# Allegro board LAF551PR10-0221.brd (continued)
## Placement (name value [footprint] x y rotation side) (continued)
PC214  0.1U_0402_10V7K  [C_0402]  95.88 47.23 0 bottom
PC215  220U 2.5V Y D2 ESR9M H1.9 SX  [C_D2]  91.41 30.94 270 bottom
PC216  1000P_0402_50V7K  [C_0402]  87.72 36.95 90 top
PC217  0.1U_0402_25V6  [C_0402]  103.17 53.7 270 top
PC218  0.1U_0402_25V6  [C_0402]  107.9 56.45 270 top
PC300  0.1U_0402_16V7K  [C_0402]  241.83 17.83 180 top
PC301  0.1U_0402_25V6  [C_0402]  259.79 23.04 0 top
PC302  2200P_0402_50V7K  [C_0402]  259.22 22.08 270 top
PC303  10U_0805_25V6K~D  [C_0805]  260.08 19.87 180 top
PC304  10U_0805_25V6K~D  [C_0805]  260.08 18.15 180 top
PC305  0.1U_0603_25V7K  [C_0603]  248.29 21.77 270 top
PC306  220U 2.5V Y D2 ESR9M H1.9 SX  [C_D2]  244.59 24.59 270 bottom
PC307  220U 2.5V Y D2 ESR9M H1.9 SX  [C_D2]  239.82 24.59 270 bottom
PC308  1U_0603_6.3V6M  [C_0603]  247.85 19.29 270 top
PC309  680P_0402_50V7K  [C_0402]  257.49 19.1 0 bottom
PC310  1U_0402_25V6K  [C_0402]  258.33 22.05 270 top
PC311  1000P_0402_50V7K  [C_0402]  259.79 23.93 0 top
PC500  2200P_0402_50V7K  [C_0402]  126.88 136.6 90 top
PC501  0.01UF_0402_25V7K  [C_0402]  125.92 133.4 180 bottom
PC502  10U_0402_6.3V6M  [C_0402]  122.18 139.93 270 bottom
PC503  1000P_0402_50V7K  [C_0402]  127.75 135.28 180 top
PC504  3300P_0402_25V7K  [C_0402]  124.8 139.2 90 bottom
PC505  2200P_0402_50V7K  [C_0402]  125.92 134.32 180 bottom
PC506  470P_0402_50V8J  [C_0402]  123.91 139.97 270 bottom
PC507  1000P_0402_50V7K  [C_0402]  126.55 139.65 180 bottom
PC508  1000P_0402_50V7K  [C_0402]  127.75 136.6 90 top
PC509  0.015U_0402_25V7K  [C_0402]  128.81 135.72 0 bottom
PC510  100P_0402_50V8J  [C_0402]  127.39 140.41 270 bottom
PC511  1000P_0402_50V7K  [C_0402]  129.73 136.58 180 top
PC512  2200P_0402_50V7K  [C_0402]  129.73 139.63 180 top
PC513  1000P_0402_50V7K  [C_0402]  119.69 135.49 270 top
PC514  2200P_0402_50V7K  [C_0402]  120.53 137.37 180 bottom
PC515  15P_0402_50V8J  [C_0402]  129.71 141.35 180 bottom
PC516  470P_0402_50V8J  [C_0402]  129.75 140.52 180 top
PC517  2200P_0402_50V7K  [C_0402]  129.73 140.49 180 bottom
PC518  470P_0402_50V8J  [C_0402]  117.05 133.68 90 top
PC519  15P_0402_50V8J  [C_0402]  119.44 141.91 90 bottom
PC520  470P_0402_50V8J  [C_0402]  127.36 141.28 180 bottom
PC521  2200P_0402_50V7K  [C_0402]  118.55 143.69 0 bottom
PC522  470P_0402_50V8J  [C_0402]  120.74 141.43 0 bottom
PC523  100P_0402_50V8J  [C_0402]  128.86 143.28 90 bottom
PC524  1000P_0402_50V7K  [C_0402]  128.86 144.2 270 top
PC525  0.22U_0402_25V6K  [C_0402]  126.53 143.89 0 bottom
PC526  100P_0402_50V8J  [C_0402]  120.34 144.25 90 bottom
PC527  0.22U_0402_25V6K  [C_0402]  120.4 146.36 0 bottom
PC528  680P_0402_50V7K  [C_0402]  121.22 144.25 90 bottom
PC529  0.1U_0402_25V6  [C_0402]  126.6 145.52 180 bottom
PC530  0.01U_0402_50V7K  [C_0402]  126.97 148.79 270 top
PC531  0.1U_0402_25V6  [C_0402]  122.41 148.21 180 bottom
PC532  1U_0603_10V6K  [C_0603]  125.92 147.93 90 top
PC533  0.1U_0402_25V6  [C_0402]  129.42 145.49 180 bottom
PC534  0.1U_0402_25V6  [C_0402]  119.74 148.21 0 bottom
PC535  0.1U_0402_25V6  [C_0402]  129.42 146.36 180 bottom
PC536  0.1U_0402_25V6  [C_0402]  129.41 148.12 180 bottom
PC537  0.1U_0402_25V6  [C_0402]  129.42 149.89 180 bottom
PC539  100U_25V_M  [C_ECST250ADA101MF611]  160.82 156.74 270 bottom
PC540  1U_0402_16V6K  [C_0402]  151.02 149.66 180 top
PC541  0.22U_0603_25V7K  [C_0603]  152.23 150.97 90 bottom
PC542  100U_25V_M  [C_ECST250ADA101MF611]  153.78 156.74 270 bottom
PC543  10U_0805_25V6K  [C_0805]  152.15 148.34 270 top
PC544  10U_0805_25V6K  [C_0805]  153.88 148.34 270 top
PC545  10U_0805_25V6K  [C_0805]  153.89 150.1 180 top
PC546  0.1U_0402_25V6  [C_0402]  156.47 147.68 270 top
PC547  2200P_0402_50V7K  [C_0402]  155.08 147.73 270 bottom
PC548  33P_0603_50V8J  [C_0603]  152.85 141.68 0 top
PC549  1U_0402_16V6K  [C_0402]  157.34 146.76 90 top
PC550  0.22U_0603_25V7K  [C_0603]  160.03 147.97 90 bottom
PC551  10U_0805_25V6K  [C_0805]  160.08 145.2 270 top
PC552  10U_0805_25V6K  [C_0805]  161.78 145.22 270 top
PC553  10U_0805_25V6K  [C_0805]  160.18 146.33 90 top
PC554  0.1U_0402_25V6  [C_0402]  158.8 146.75 270 top
PC555  2200P_0402_50V7K  [C_0402]  162.8 145.14 270 bottom
PC556  33P_0603_50V8J  [C_0603]  160.67 137.86 0 top
PC557  1U_0402_16V6K  [C_0402]  166.81 143.68 90 top
PC558  0.22U_0603_25V7K  [C_0603]  167.64 147.98 90 bottom
PC559  10U_0805_25V6K  [C_0805]  170.19 145.11 270 top
PC560  10U_0805_25V6K  [C_0805]  170.25 146.23 90 top
PC561  10U_0805_25V6K  [C_0805]  168.47 145.15 270 top
PC562  0.1U_0402_25V6  [C_0402]  170.42 145.65 270 bottom
PC563  2200P_0402_50V7K  [C_0402]  171.28 145.62 270 bottom
PC564  33P_0603_50V8J  [C_0603]  168.27 137.86 0 top
PC565  10U_0805_25V6K  [C_0805]  145.39 149.79 180 top
PC566  1U_0402_16V6K  [C_0402]  142.71 149.34 180 top
PC567  0.22U_0603_25V7K  [C_0603]  143.62 151.57 90 bottom
PC568  10U_0805_25V6K  [C_0805]  143.88 148.35 270 top
PC569  10U_0805_25V6K  [C_0805]  145.59 148.35 270 top
PC570  680P_0603_50V7K  [C_0603]  145.39 141.62 0 top
PC571  0.1U_0402_25V6  [C_0402]  147.43 147.53 270 bottom
PC572  2200P_0402_50V7K  [C_0402]  146.39 149.65 90 top
PC573  1U_0402_16V6K  [C_0402]  174.7 146.13 180 top
PC574  0.22U_0603_25V7K  [C_0603]  176.15 148.03 90 bottom
PC575  10U_0805_25V6K  [C_0805]  176.87 144.82 270 top
PC576  10U_0805_25V6K  [C_0805]  178.6 144.82 270 top
PC577  10U_0805_25V6K  [C_0805]  177.24 145.94 90 top
PC578  0.1U_0402_25V6  [C_0402]  178.42 148.56 0 bottom
PC579  2200P_0402_50V7K  [C_0402]  178.42 147.67 0 bottom
PC580  33P_0603_50V8J  [C_0603]  177.18 137.86 0 top
PC581  2200P_0402_50V7K  [C_0402]  185.57 148.02 0 bottom
PC582  0.1U_0402_25V6  [C_0402]  186.76 146.89 45 bottom
PC583  10U_0805_25V6K  [C_0805]  184.79 144.86 270 top
PC584  10U_0805_25V6K  [C_0805]  185.71 149.32 0 bottom
PC585  10U_0805_25V6K  [C_0805]  183.08 144.86 270 top
PC586  0.22U_0603_25V7K  [C_0603]  183.33 147.96 90 bottom
PC587  680P_0603_50V7K  [C_0603]  184.59 136.2 0 top
PC588  1U_0402_16V6K  [C_0402]  180.81 146.49 0 top
PC589  2200P_0402_50V7K  [C_0402]  118.64 119.18 180 bottom
PC590  0.22U_0402_10V6K  [C_0402]  124.58 119.5 0 bottom
PC591  680P_0603_50V7K  [C_0603]  118.44 109.91 270 bottom
PC592  10U_0805_25V6K  [C_0805]  120 121.53 0 bottom
PC593  0.1U_0603_25V7K  [C_0603]  119.45 114.93 0 bottom
PC594  0.1U_0402_25V6  [C_0402]  118.64 118.29 180 bottom
PC596  22U_0603_6.3V6M  [C_0603]  122.62 105.66 180 bottom
PC597  22U_0603_6.3V6M  [C_0603]  122.62 106.99 180 bottom
PC598  22U_0603_6.3V6M  [C_0603]  124.78 106.99 0 bottom
PC599  22U_0603_6.3V6M  [C_0603]  124.78 105.66 0 bottom
PC701  0.1U_0402_25V6  [C_0402]  58.05 30.47 180 top
PC702  0.047U_0402_25V7K  [C_0402]  61.78 25.01 0 top
PC703  0.1U_0402_25V6  [C_0402]  64.33 29.01 270 top
PC704  2200P_0402_50V7K  [C_0402]  63.45 29.01 270 top
PC705  10U_0805_25V6K~D  [C_0805]  65.73 28.88 270 top
PC706  10U_0805_25V6K~D  [C_0805]  67.51 28.88 270 top
PC707  0.1U_0603_25V7K  [C_0603]  58.37 24.41 90 bottom
PC708  0.1U_0402_25V6  [C_0402]  58.48 27.55 0 bottom
PC709  0.01UF_0402_25V7K  [C_0402]  59.64 26.36 270 bottom
PC710  2.2U_0603_10V7K  [C_0603]  59.23 23.17 180 bottom
PC711  1U_0603_25V6K  [C_0603]  59.44 24.44 0 bottom
PC712  22U_0805_25V6M  [C_0805]  82.47 28.71 90 bottom
PC713  22U_0805_25V6M  [C_0805]  84.18 28.71 90 bottom
PC714  22U_0805_25V6M  [C_0805]  86.03 28.74 90 bottom
PC715  680P_0402_50V7K  [C_0402]  63.76 22.84 90 top
PC716  0.1U_0402_25V6  [C_0402]  57.4 17.71 0 top
PC717  0.1U_0402_25V6  [C_0402]  58.31 18.6 180 top
PC718  100P_0402_50V8J  [C_0402]  52.96 26.49 0 top
PC719  0.01UF_0402_25V7K  [C_0402]  56.34 26.66 270 bottom
PC720  100P_0402_50V8J  [C_0402]  52.97 25.6 0 top
PC721  0.1U_0402_25V6  [C_0402]  56.52 18.61 270 top
PC722  1000P_0402_50V7K  [C_0402]  70.11 42.36 180 top
PC723  1000P_0402_50V7K  [C_0402]  69.92 35.17 180 top
PC725  0.022U_0603_25V7K  [C_0603]  79.93 30.14 90 top
PC726  1000P_0402_50V7K  [C_0402]  62.56 29.02 270 top
PC727  1U_0402_25V6K  [C_0402]  61.67 29.02 270 top
PC800  10U_0805_25V6K~D  [C_0805]  245.12 40.57 90 bottom
PC801  0.1U_0402_16V7K  [C_0402]  238.08 41.65 180 bottom
PC802  680P_0402_50V7K  [C_0402]  247.8 47.11 0 bottom
PC803  2.2U_0402_16V6K  [C_0402]  241.31 44.58 270 top
PC804  22U_0603_6.3V6M  [C_0603]  240.42 48.38 90 bottom
PC805  22U_0603_6.3V6M  [C_0603]  239.15 48.38 90 bottom
PC806  680P_0402_50V7K  [C_0402]  234.44 45.84 0 bottom
PC807  2.2U_0402_16V6K  [C_0402]  122.61 115.24 0 bottom
PC808  0.1U_0603_25V7K  [C_0603]  248.62 44.75 180 bottom
PC809  330P_0402_50V7K  [C_0402]  237.17 45.2 0 bottom
PC810  10U_0805_25V6K~D  [C_0805]  229.93 37.2 0 bottom
PC811  0.1U_0402_16V7K  [C_0402]  226.07 40.36 90 bottom
PC812  22U_0603_6.3V6M  [C_0603]  224.86 46.61 270 bottom
PC813  22U_0603_6.3V6M  [C_0603]  223.59 46.61 270 bottom
PC814  10U_0805_25V6K~D  [C_0805]  229.85 38.92 0 bottom
PC815  22U_0603_6.3V6M  [C_0603]  236.67 48.38 90 bottom
PC816  22U_0603_6.3V6M  [C_0603]  237.94 48.38 90 bottom
PC817  1U_0603_6.3V6M  [C_0603]  239.14 46.1 0 bottom
PC818  330P_0402_50V7K  [C_0402]  124.65 125.17 180 bottom
PC819  330P_0402_50V7K  [C_0402]  222.51 44.64 270 bottom
PC820  22U_0603_6.3V6M  [C_0603]  224.86 47.58 90 bottom
PC821  1U_0603_6.3V6M  [C_0603]  226.13 44.12 180 bottom
PC822  2.2U_0402_16V6K  [C_0402]  229.56 45.15 180 bottom
PC823  0.1U_0603_25V7K  [C_0603]  234.07 44.25 180 bottom
PC824  22U_0603_6.3V6M  [C_0603]  223.59 47.58 90 bottom
PC1000  220U_D7_2VM_R6M  [C_EEFSS0D221R]  164.07 127.12 0 bottom
PC1001  220U 2.5V Y D2 ESR9M H1.9 SX  [C_D2]  170.89 127.15 0 top
PC1002  220U 2.5V Y D2 ESR9M H1.9 SX  [C_D2]  161.7 127.18 180 top
PC1003  47U_0603_6.3V6M  [C_0603]  177.04 128.48 270 bottom
PC1004  47U_0603_6.3V6M  [C_0603]  175.14 128.48 270 bottom
PC1005  47U_0805_6.3V6M  [C_0805]  164.77 108.89 0 top
PC1006  47U_0603_6.3V6M  [C_0603]  178.95 128.48 270 bottom
PC1007  220U 2.5V Y D2 ESR9M H1.9 SX  [C_D2]  145.91 132.2 0 top
PC1008  220U_D7_2VM_R6M  [C_EEFSS0D221R]  143.11 128.01 0 bottom
PC1009  220U_D7_2VM_R6M  [C_EEFSS0D221R]  151.67 127.31 180 top
PC1010  220U_D7_2VM_R6M  [C_EEFSS0D221R]  155.58 113.42 0 top
PC1011  47U_0603_6.3V6M  [C_0603]  136.6 110.86 180 top
PC1012  47U_0603_6.3V6M  [C_0603]  145.49 113.27 0 top
PC1013  47U_0603_6.3V6M  [C_0603]  136.34 115.69 180 top
PC1014  47U_0805_6.3V6M  [C_0805]  184.64 130.48 0 top
PC1015  47U_0805_6.3V6M  [C_0805]  184.64 132.2 0 top
PC1016  47U_0805_6.3V6M  [C_0805]  179.68 130.55 180 top
PC1017  220U_D2_2.5VY_R9M  [C_D2]  180.83 127.18 0 top
PC1018  47U_0805_6.3V6M  [C_0805]  164.77 110.61 0 top
PC1019  10U_0402_6.3V6M  [C_0402]  165.5 113.75 0 top
PC1020  22U_0603_6.3V6M  [C_0603]  156.86 109.46 0 top
PC1021  22U_0603_6.3V6M  [C_0603]  156.86 108.26 0 top
PC1022  22U_0603_6.3V6M  [C_0603]  155.91 109.46 180 top
PC1023  22U_0603_6.3V6M  [C_0603]  155.91 108.26 180 top
PC1024  22U_0603_6.3V6M  [C_0603]  160.61 108.26 180 top
PC1025  22U_0603_6.3V6M  [C_0603]  160.61 109.46 180 top
PC1026  22U_0603_6.3V6M  [C_0603]  161.56 109.46 0 top
PC1027  22U_0603_6.3V6M  [C_0603]  161.56 108.26 0 top
PC1028  22U_0603_6.3V6M  [C_0603]  140.73 109.84 0 top
PC1029  22U_0603_6.3V6M  [C_0603]  138.38 109.84 0 top
PC1030  22U_0603_6.3V6M  [C_0603]  140.87 106.93 180 top
PC1031  22U_0603_6.3V6M  [C_0603]  143.08 109.84 0 top
PC1032  22U_0603_6.3V6M  [C_0603]  144.69 108.22 180 top
PC1033  22U_0603_6.3V6M  [C_0603]  140.87 108.18 180 top
PC1034  22U_0603_6.3V6M  [C_0603]  144.69 106.9 180 top
PC1036  10U_0402_6.3V6M  [C_0402]  164.68 112.83 180 top
PC1037  10U_0402_6.3V6M  [C_0402]  164.76 116.54 180 top
PC1038  10U_0402_6.3V6M  [C_0402]  165.58 116.26 0 top
PC1039  10U_0402_6.3V6M  [C_0402]  164.68 113.72 180 top
PC1040  10U_0402_6.3V6M  [C_0402]  164.68 111.94 180 top
PC1041  10U_0402_6.3V6M  [C_0402]  165.55 111.94 0 top
PC1042  1U_0201_6.3V6M  [C_0201]  164.82 115.82 180 top
PC1043  22U_0603_6.3V6M  [C_0603]  183.51 127.83 0 bottom
PC1044  22U_0603_6.3V6M  [C_0603]  165.14 114.78 0 top
PC1045  10U_0402_6.3V6M  [C_0402]  150.48 115.58 0 top
PC1046  10U_0402_6.3V6M  [C_0402]  147.17 110.01 180 top
PC1047  10U_0402_6.3V6M  [C_0402]  153.2 110.29 180 top
PC1048  10U_0402_6.3V6M  [C_0402]  147.17 110.88 180 top
PC1049  10U_0402_6.3V6M  [C_0402]  153.13 113.32 180 top
PC1050  10U_0402_6.3V6M  [C_0402]  148.02 111.23 0 top
PC1051  10U_0402_6.3V6M  [C_0402]  150.47 113.31 0 top
PC1052  10U_0402_6.3V6M  [C_0402]  146.9 104.58 180 top
PC1053  10U_0402_6.3V6M  [C_0402]  157.33 104.8 180 top
PC1054  10U_0402_6.3V6M  [C_0402]  157.25 106.13 180 top
PC1055  10U_0402_6.3V6M  [C_0402]  153.37 104.93 0 top
PC1056  10U_0402_6.3V6M  [C_0402]  158.09 106.13 0 top
PC1057  10U_0402_6.3V6M  [C_0402]  157.41 107.22 0 top
PC1058  10U_0402_6.3V6M  [C_0402]  153.13 114.5 180 top
PC1059  10U_0402_6.3V6M  [C_0402]  140.87 112.87 0 top
PC1060  10U_0402_6.3V6M  [C_0402]  145.87 114.35 0 top
PC1061  10U_0402_6.3V6M  [C_0402]  143.33 113.97 0 top
PC1062  10U_0402_6.3V6M  [C_0402]  145.57 112.21 0 top
PC1063  10U_0402_6.3V6M  [C_0402]  145.85 116.01 0 top
PC1064  10U_0402_6.3V6M  [C_0402]  140.87 111.43 0 top
PC1065  10U_0402_6.3V6M  [C_0402]  138.6 111.49 0 top
PC1066  10U_0402_6.3V6M  [C_0402]  138.62 112.86 0 top
PC1067  10U_0402_6.3V6M  [C_0402]  143.19 112.23 0 top
PC1068  10U_0402_6.3V6M  [C_0402]  143.51 116.04 0 top
PC1071  10U_0402_6.3V6M  [C_0402]  160.07 107.22 180 top
PC1072  10U_0402_6.3V6M  [C_0402]  159.82 106.12 0 top
PC1073  10U_0402_6.3V6M  [C_0402]  148.02 109.65 0 top
PC1074  10U_0402_6.3V6M  [C_0402]  147.98 112.57 0 top
PC1075  10U_0402_6.3V6M  [C_0402]  151.58 104.34 180 top
PC1076  10U_0402_6.3V6M  [C_0402]  163.3 106.99 0 top
PC1077  10U_0402_6.3V6M  [C_0402]  162.46 106.12 180 top
PC1078  10U_0402_6.3V6M  [C_0402]  152.29 108.43 180 top
PC1079  10U_0402_6.3V6M  [C_0402]  163.3 106.12 0 top
PC1080  10U_0402_6.3V6M  [C_0402]  150.5 112.09 0 top
PC1081  10U_0402_6.3V6M  [C_0402]  165.94 106.99 180 top
PC1082  10U_0402_6.3V6M  [C_0402]  150.51 110.78 0 top
PC1083  10U_0402_6.3V6M  [C_0402]  148.55 114.75 0 top
PC1084  10U_0402_6.3V6M  [C_0402]  155.35 106.2 180 top
PC1097  1U_0201_6.3V6M  [C_0201]  163.12 102.92 180 top
PC1098  1U_0201_6.3V6M  [C_0201]  164.62 104.94 180 top
PC1099  1U_0201_6.3V6M  [C_0201]  165.81 126.74 270 top
PC1100  1U_0201_6.3V6M  [C_0201]  155.1 106.91 180 top
PC1101  1U_0201_6.3V6M  [C_0201]  165.27 104.94 0 top
PC1102  1U_0201_6.3V6M  [C_0201]  158.65 103.79 90 top
PC1103  1U_0201_6.3V6M  [C_0201]  159.22 103.79 90 top
PC1104  1U_0201_6.3V6M  [C_0201]  162.89 103.49 180 top
PC1105  1U_0201_6.3V6M  [C_0201]  162.23 110.8 180 top
PC1106  1U_0201_6.3V6M  [C_0201]  166.57 105.68 0 top
PC1107  1U_0201_6.3V6M  [C_0201]  161.98 116.07 180 top
PC1108  1U_0201_6.3V6M  [C_0201]  161.98 116.64 180 top
PC1109  1U_0201_6.3V6M  [C_0201]  162.57 116.64 0 top
PC1110  1U_0201_6.3V6M  [C_0201]  162.57 116.07 0 top
PC1111  1U_0201_6.3V6M  [C_0201]  160.44 110.8 0 top
PC1123  1U_0201_6.3V6M  [C_0201]  155.37 116.08 0 top
PC1124  1U_0201_6.3V6M  [C_0201]  160.19 116.06 0 top
PC1125  1U_0201_6.3V6M  [C_0201]  166.66 107.12 90 top
PC1126  1U_0201_6.3V6M  [C_0201]  166.57 105.12 0 top
PC1127  1U_0201_6.3V6M  [C_0201]  157.77 116.07 0 top
PC1128  1U_0201_6.3V6M  [C_0201]  157.15 116.64 180 top
PC1129  1U_0201_6.3V6M  [C_0201]  164.62 104.37 180 top
PC1130  1U_0201_6.3V6M  [C_0201]  157.15 116.07 180 top
PC1131  1U_0201_6.3V6M  [C_0201]  159.56 116.64 180 top
PC1132  1U_0201_6.3V6M  [C_0201]  154.74 116.63 180 top
PC1133  1U_0201_6.3V6M  [C_0201]  154.74 116.07 180 top
PC1134  1U_0201_6.3V6M  [C_0201]  163.74 102.92 0 top
PC1135  1U_0201_6.3V6M  [C_0201]  148.45 115.46 0 top
PC1136  1U_0201_6.3V6M  [C_0201]  162.86 110.8 0 top
PC1137  1U_0201_6.3V6M  [C_0201]  160.44 104.95 0 top
PC1138  1U_0201_6.3V6M  [C_0201]  142.74 116.13 180 top
PC1139  1U_0201_6.3V6M  [C_0201]  140.3 114.6 180 top
PC1140  1U_0201_6.3V6M  [C_0201]  144.03 105.71 180 top
PC1141  1U_0201_6.3V6M  [C_0201]  140.28 116.18 180 top
PC1142  1U_0201_6.3V6M  [C_0201]  140.97 114.14 0 top
PC1143  1U_0201_6.3V6M  [C_0201]  141.57 105.58 180 top
PC1144  1U_0201_6.3V6M  [C_0201]  140.95 115.61 0 top
PC1145  1U_0201_6.3V6M  [C_0201]  138.54 114.45 0 top
PC1146  1U_0201_6.3V6M  [C_0201]  139.18 105.26 180 top
PC1147  1U_0201_6.3V6M  [C_0201]  144.03 104.92 180 top
PC1148  1U_0201_6.3V6M  [C_0201]  141.58 104.98 180 top
PC1149  1U_0201_6.3V6M  [C_0201]  138.53 115.7 0 top
PC1161  1U_0201_6.3V6M  [C_0201]  166.38 126.74 270 top
PC1162  1U_0201_6.3V6M  [C_0201]  164.41 125.15 0 top
PC1163  1U_0201_6.3V6M  [C_0201]  162.23 104.95 180 top
PC1164  1U_0201_6.3V6M  [C_0201]  162.86 104.95 0 top
PC1165  1U_0201_6.3V6M  [C_0201]  158.03 104.95 0 top
PC1166  1U_0201_6.3V6M  [C_0201]  158.62 110.8 180 top
PC1167  1U_0201_6.3V6M  [C_0201]  159.82 104.95 180 top
PC1168  1U_0201_6.3V6M  [C_0201]  160.16 116.64 0 top
PC1169  1U_0201_6.3V6M  [C_0201]  156.78 110.8 0 top
PC1170  1U_0201_6.3V6M  [C_0201]  152.68 115.69 180 top
PC1171  1U_0201_6.3V6M  [C_0201]  149.6 116.51 270 top
PC1172  1U_0201_6.3V6M  [C_0201]  150.79 116.29 0 top
PC1173  1U_0201_6.3V6M  [C_0201]  157.8 116.64 0 top
PC1174  1U_0201_6.3V6M  [C_0201]  155.39 116.65 0 top
PC1175  1U_0201_6.3V6M  [C_0201]  159.57 116.07 180 top
PC1199  47U_0603_6.3V6M  [C_0603]  147.78 108.18 180 top
PC1200  22U_0603_6.3V6M  [C_0603]  150.14 108.17 180 top
PC1201  22U_0603_6.3V6M  [C_0603]  147.78 106.91 180 top
PC1202  22U_0603_6.3V6M  [C_0603]  152.5 106.9 180 top
PC1203  22U_0603_6.3V6M  [C_0603]  150.14 106.91 180 top
PC1204  10U_0402_6.3V6M  [C_0402]  150.54 109.58 0 top
PC1205  10U_0402_6.3V6M  [C_0402]  150.48 114.71 0 top
PC1206  10U_0402_6.3V6M  [C_0402]  148.07 113.89 0 top
PC1207  10U_0402_6.3V6M  [C_0402]  164.21 125.9 0 top
PC1208  10U_0402_6.3V6M  [C_0402]  149.2 104.95 180 top
PC1209  10U_0402_6.3V6M  [C_0402]  151.56 105.21 180 top
PC1210  10U_0402_6.3V6M  [C_0402]  155.44 103.56 180 top
PC1236  1U_0201_6.3V6M  [C_0201]  146.66 105.29 180 top
PC1237  1U_0201_6.3V6M  [C_0201]  165.29 104.37 0 top
PC1238  1U_0201_6.3V6M  [C_0201]  154.99 110.8 180 top
PC1300  22U_0603_6.3V6M  [C_0603]  101.71 53.76 0 bottom
PC1301  0.1U_0402_16V7K  [C_0402]  100.12 52.52 90 bottom
PC1303  22U_0603_6.3V6M  [C_0603]  101.1 40.44 180 bottom
PC1304  22U_0603_6.3V6M  [C_0603]  101.1 41.65 180 bottom
PC1305  22P_0603_50V8  [C_0603]  101.1 42.85 180 bottom
PC1306  22U_0603_6.3V6M  [C_0603]  101.71 52.55 0 bottom
PC1307  1U_0603_6.3V6M  [C_0603]  104.18 51.43 270 bottom
PC5002  2.2U_0402_10V6M  [C_0402]  180.83 144.85 270 top
PC5003  1U_0603_6.3V6M  [C_0603]  124.53 115.43 0 bottom
PC5005  2.2U_0402_10V6M  [C_0402]  147.71 152.15 270 bottom
PC5006  2.2U_0402_10V6M  [C_0402]  157.03 145.05 270 top
PC5007  2.2U_0402_10V6M  [C_0402]  164.63 143.83 270 top
PC5008  2.2U_0402_10V6M  [C_0402]  141.66 148.28 270 top
PC5009  2.2U_0402_10V6M  [C_0402]  173.36 145.02 270 top
PC5013  1U_0402_25V6K  [C_0402]  154.87 150.42 0 top
PC5014  1000P_0402_50V7K  [C_0402]  155.61 147.7 270 top
PC5015  1U_0402_25V6K  [C_0402]  163.01 147.81 90 bottom
PC5016  1000P_0402_50V7K  [C_0402]  161.49 146.21 90 top
PC5017  1U_0402_25V6K  [C_0402]  168.6 147.36 90 top
PC5018  1000P_0402_50V7K  [C_0402]  170.44 147.69 90 bottom
PC5019  1U_0402_25V6K  [C_0402]  146.87 147.77 270 top
PC5020  1000P_0402_50V7K  [C_0402]  147.73 147.77 270 top
PC5021  1U_0402_25V6K  [C_0402]  178.55 147.62 90 top
PC5022  1000P_0402_50V7K  [C_0402]  179.41 147.62 90 top
PC5023  1U_0402_25V6K  [C_0402]  186.11 144.45 270 top
PC5024  1000P_0402_50V7K  [C_0402]  186.98 144.45 270 top
PC5025  1U_0402_25V6K  [C_0402]  118.64 121.02 180 bottom
PC5026  1000P_0402_50V7K  [C_0402]  118.63 120.1 180 bottom
PC6000  0.1U_0402_25V6  [C_0402]  267.29 145.1 180 bottom
PC6001  0.1U_0402_25V6  [C_0402]  270.68 139.44 180 bottom
PC6002  0.01U_0402_16V7K  [C_0402]  267.29 142.42 180 bottom
PC6003  0.1U_0402_25V6  [C_0402]  266.9 133.86 270 bottom
PC6004  0.1U_0402_25V6  [C_0402]  266.9 135.77 270 bottom
PC6005  0.015U_0402_16V7K  [C_0402]  268.88 143.88 270 bottom
PC6006  0.12U_0402_10V6K  [C_0402]  266.9 139.51 270 bottom
PC6007  0.1U_0402_25V6  [C_0402]  269.74 143.88 0 bottom
PC6008  0.1U_0402_10V6K  [C_0402]  269.73 136.74 0 bottom
PC6009  0.1U_0402_25V6  [C_0402]  272.42 146.62 270 bottom
PC6010  0.1U_0402_25V6  [C_0402]  273.31 145.71 90 bottom
PC6011  0.1U_0402_25V6  [C_0402]  270.65 146.62 270 bottom
PC6012  0.1U_0402_25V6  [C_0402]  274.2 146.62 270 bottom
PC6014  1U_0402_6.3V6K  [C_0402]  276.23 137.58 90 top
PC6015  4700P_0402_50V7K  [C_0402]  281.81 141.85 0 bottom
PC6016  0.01U_0402_16V  [C_0402]  277.49 141.09 0 top
PC6017  0.1U_0402_25V6  [C_0402]  270.66 141.21 180 bottom
PC6100  0.1U_0402_25V6  [C_0402]  260.68 152.12 90 bottom
PC6101  1U_0603_16V7  [C_0603]  254.92 153.24 270 top
PC6102  0.1U_0603_50V7K  [C_0603]  256.17 156.07 270 top
PC6103  1U_0603_16V7  [C_0603]  250.71 150.99 270 top
PC6104  2200P_0402_50V7K  [C_0402]  261.57 152.12 90 bottom
PC6105  0.1U_0402_25V6  [C_0402]  264.28 148.36 270 bottom
PC6106  2200P_0402_50V7K  [C_0402]  265.16 148.36 270 bottom
PC6107  10U_0805_25V6K~D  [C_0805]  261.06 150.45 270 bottom
PC6108  470U_D2_2VM_R4.5M~D  [C_D1]  234.46 135.56 180 top
PC6109  10U_0805_25V6K~D  [C_0805]  259.28 150.45 270 bottom
PC6110  10U_0805_25V6K~D  [C_0805]  259.28 152.3 90 bottom
PC6111  10U_0805_25V6K~D  [C_0805]  262.9 150.45 270 bottom
PC6112  33U_D2_25VM_R40M  [C_EEFCX1E330R]  261.57 153.58 90 top
PC6113  3300P_0805_50V7K  [C_0805]  259.76 144.86 0 top
PC6114  1U_0603_16V7  [C_0603]  241.03 153.2 270 top
PC6115  0.1U_0603_50V7K  [C_0603]  242.32 156.07 270 top
PC6116  1U_0603_16V7  [C_0603]  236.93 150.93 270 top
PC6117  0.1U_0402_25V6  [C_0402]  246.9 152.06 90 bottom
PC6118  2200P_0402_50V7K  [C_0402]  247.79 152.06 90 bottom
PC6119  0.1U_0402_25V6  [C_0402]  250.25 150.1 270 bottom
PC6120  2200P_0402_50V7K  [C_0402]  251.13 150.1 270 bottom
PC6121  10U_0805_25V6K~D  [C_0805]  245.5 150.38 270 bottom
PC6122  10U_0805_25V6K~D  [C_0805]  247.23 150.38 270 bottom
PC6123  33U_D2_25VM_R40M  [C_EEFCX1E330R]  247.72 153.52 90 top
PC6124  470U_D2_2VM_R4.5M~D  [C_D1]  225.45 135.5 180 top
PC6125  10U_0805_25V6K~D  [C_0805]  248.94 150.36 270 bottom
PC6126  10U_0805_25V6K~D  [C_0805]  245.5 152.24 90 bottom
PC6127  3300P_0805_50V7K  [C_0805]  245.98 144.8 0 top
PC6200  0.1U_0402_25V6  [C_0402]  233.18 152 90 bottom
PC6201  1U_0603_16V7  [C_0603]  227.24 153.23 270 top
PC6202  0.1U_0603_50V7K  [C_0603]  228.67 155.95 270 top
PC6203  1U_0603_16V7  [C_0603]  222.98 156.24 180 top
PC6204  2200P_0402_50V7K  [C_0402]  234.07 152 90 bottom
PC6205  0.1U_0402_25V6  [C_0402]  236.46 150.12 270 bottom
PC6206  2200P_0402_50V7K  [C_0402]  237.33 150.12 270 bottom
PC6207  470U_D2_2VM_R4.5M~D  [C_D1]  245.81 123.94 0 bottom
PC6208  10U_0805_25V6K~D  [C_0805]  231.78 152.17 90 bottom
PC6209  10U_0805_25V6K~D  [C_0805]  235.16 150.31 270 bottom
PC6210  10U_0805_25V6K~D  [C_0805]  233.43 150.3 270 bottom
PC6211  10U_0805_25V6K~D  [C_0805]  231.71 150.3 270 bottom
PC6212  33U_D2_25VM_R40M  [C_EEFCX1E330R]  233.94 153.46 90 top
PC6213  3300P_0805_50V7K  [C_0805]  232.2 144.67 0 top
PC6214  1U_0603_16V7  [C_0603]  212.73 154.8 90 bottom
PC6215  0.1U_0603_50V7K  [C_0603]  214.89 155.91 270 bottom
PC6216  1U_0603_16V7  [C_0603]  209.62 149.98 270 bottom
PC6217  1U_0402_25V6K  [C_0402]  221.05 152.19 90 top
PC6218  1000P_0402_50V7K  [C_0402]  220.16 152.19 90 top
PC6219  0.1U_0402_25V6  [C_0402]  223.68 149.43 270 bottom
PC6220  2200P_0402_50V7K  [C_0402]  222.82 149.43 270 bottom
PC6221  470U_D2_2VM_R4.5M~D  [C_D1]  243.61 135.56 180 top
PC6222  10U_0805_25V6K~D  [C_0805]  216.42 154.59 90 bottom
PC6223  10U_0805_25V6K~D  [C_0805]  221.52 150.23 270 bottom
PC6224  10U_0805_25V6K~D  [C_0805]  219.81 150.23 270 bottom
PC6225  10U_0805_25V6K~D  [C_0805]  218.08 150.23 270 bottom
PC6226  33U_D2_25VM_R40M  [C_EEFCX1E330R]  219.72 152.73 270 bottom
PC6227  3300P_0805_50V7K  [C_0805]  207.23 143.95 0 bottom
PC6300  1U_0402_6.3V6K  [C_0402]  245.83 96.84 270 top
PC6301  1U_0402_6.3V6K  [C_0402]  242.41 97.83 270 top
PC6302  1U_0402_6.3V6K  [C_0402]  242.45 91.44 270 top
PC6303  1U_0402_6.3V6K  [C_0402]  227.67 106.34 90 top
PC6304  1U_0402_6.3V6K  [C_0402]  246.01 102.59 90 top
PC6305  1U_0402_6.3V6K  [C_0402]  231.23 107.06 270 top
PC6306  1U_0402_6.3V6K  [C_0402]  231.23 105.27 270 top
PC6307  1U_0402_6.3V6K  [C_0402]  231.23 102.59 90 top
PC6308  1U_0402_6.3V6K  [C_0402]  232.63 107.93 90 top
PC6309  1U_0402_6.3V6K  [C_0402]  234.02 107.93 90 top
PC6310  1U_0402_6.3V6K  [C_0402]  232.63 107.06 270 top
PC6311  1U_0402_6.3V6K  [C_0402]  234.02 107.06 270 top
PC6312  1U_0402_6.3V6K  [C_0402]  239.61 96.08 270 top
PC6313  1U_0402_6.3V6K  [C_0402]  239.61 97.83 270 top
PC6314  1U_0402_6.3V6K  [C_0402]  243.8 92.69 90 top
PC6315  1U_0402_6.3V6K  [C_0402]  243.8 98.29 270 top
PC6316  1U_0402_6.3V6K  [C_0402]  243.8 102.61 270 top
PC6317  1U_0402_6.3V6K  [C_0402]  244.63 107.55 180 top
PC6318  1U_0402_6.3V6K  [C_0402]  229.83 107.94 90 top
PC6319  1U_0402_6.3V6K  [C_0402]  229.83 100.89 90 top
PC6320  1U_0402_6.3V6K  [C_0402]  229.83 100.02 270 top
PC6321  1U_0402_6.3V6K  [C_0402]  243.8 105.78 90 top
PC6322  1U_0402_6.3V6K  [C_0402]  240.94 94.3 270 top
PC6323  1U_0402_6.3V6K  [C_0402]  253.06 119.87 90 top
PC6324  1U_0402_6.3V6K  [C_0402]  227.78 102.28 90 top
PC6325  1U_0402_6.3V6K  [C_0402]  240.94 99.58 270 top
PC6326  1U_0402_6.3V6K  [C_0402]  239.61 99.58 270 top
PC6327  1U_0402_6.3V6K  [C_0402]  252.23 114.1 0 top
PC6328  1U_0402_6.3V6K  [C_0402]  246.01 98.28 90 top
PC6329  1U_0402_6.3V6K  [C_0402]  245.82 105.29 270 top
PC6330  1U_0402_6.3V6K  [C_0402]  231.23 107.93 90 top
PC6331  1U_0402_6.3V6K  [C_0402]  227.74 100.05 90 top
PC6332  1U_0402_6.3V6K  [C_0402]  252.23 115.12 0 top
PC6333  1U_0402_6.3V6K  [C_0402]  240.94 97.83 270 top
PC6334  1U_0402_6.3V6K  [C_0402]  239.61 94.29 270 top
PC6335  1U_0402_6.3V6K  [C_0402]  254.33 117.2 90 top
PC6336  1U_0402_6.3V6K  [C_0402]  229.83 102.73 90 top
PC6337  1U_0402_6.3V6K  [C_0402]  243.8 95.62 270 top
PC6338  1U_0402_6.3V6K  [C_0402]  243.8 100.14 270 top
PC6339  1U_0402_6.3V6K  [C_0402]  243.8 104.97 270 top
PC6340  1U_0402_6.3V6K  [C_0402]  229.83 105.65 270 top
PC6341  1U_0402_6.3V6K  [C_0402]  229.83 95.37 90 top
PC6342  1U_0402_6.3V6K  [C_0402]  229.77 92.62 90 top
PC6343  1U_0402_6.3V6K  [C_0402]  229.83 98.26 270 top
PC6344  1U_0402_6.3V6K  [C_0402]  252.23 113.08 0 top
PC6345  1U_0402_6.3V6K  [C_0402]  227.8 97.02 270 top
PC6346  1U_0402_6.3V6K  [C_0402]  242.34 94.3 270 top
PC6347  1U_0402_6.3V6K  [C_0402]  245.9 107.31 270 top
PC6348  1U_0402_6.3V6K  [C_0402]  232.63 102.59 90 top
PC6349  1U_0402_6.3V6K  [C_0402]  232.63 105.27 270 top
PC6350  1U_0402_6.3V6K  [C_0402]  233.27 90.54 180 top
PC6351  1U_0402_6.3V6K  [C_0402]  234.02 102.59 90 top
PC6352  1U_0402_6.3V6K  [C_0402]  255.79 108.59 270 top
PC6353  1U_0402_6.3V6K  [C_0402]  227.8 94.35 90 top
PC6354  1U_0402_6.3V6K  [C_0402]  254.01 108.59 270 top
PC6355  1U_0402_6.3V6K  [C_0402]  247.35 107.94 0 top
PC6356  1U_0402_6.3V6K  [C_0402]  234.02 105.27 270 top
PC6357  1U_0402_6.3V6K  [C_0402]  253.95 119.87 90 top
PC6358  1U_0402_6.3V6K  [C_0402]  239.61 90.53 90 top
PC6359  22U_0805_6.3VAM  [C_0805]  247.11 116.64 180 top
PC6360  47U_0805_6.3V6M  [C_0805]  250.81 116.32 180 top
PC6361  10U_0603_6.3V6M  [C_0603]  237.52 92.83 180 top
PC6362  10U_0603_6.3V6M  [C_0603]  237.52 97.4 180 top
PC6363  470U_D2_2VM_R4.5M~D  [C_D1]  277.43 64.57 0 top
PC6364  1U_0402_6.3V6K  [C_0402]  240.94 96.08 270 top
PC6365  1U_0402_6.3V6K  [C_0402]  240.94 90.53 90 top
PC6366  1U_0402_6.3V6K  [C_0402]  254.9 108.59 270 top
PC6367  1U_0402_6.3V6K  [C_0402]  242.41 99.58 270 top
PC6368  1U_0402_6.3V6K  [C_0402]  242.34 96.08 270 top
PC6369  1U_0402_6.3V6K  [C_0402]  253.44 117.2 90 top
PC6370  22U_0805_6.3VAM  [C_0805]  249.29 114.1 180 top
PC6371  22U_0805_6.3VAM  [C_0805]  247.26 112 180 top
PC6372  22U_0805_6.3VAM  [C_0805]  248.84 112 0 top
PC6373  47U_0805_6.3V6M  [C_0805]  245.35 109.88 180 top
PC6374  4.7U_0603_6.3V6K  [C_0603]  276.68 67.62 0 top
PC6375  4.7U_0603_6.3V6K  [C_0603]  276.68 68.89 0 top
PC6376  10U_0603_6.3V6M  [C_0603]  237.52 102.16 180 top
PC6377  10U_0603_6.3V6M  [C_0603]  237.52 105.08 180 top
PC6378  47U_0805_6.3V6M  [C_0805]  288.97 72 0 bottom
PC6379  4.7U_0603_6.3V6K  [C_0603]  233.82 130.36 0 bottom
PC6380  4.7U_0603_6.3V6K  [C_0603]  256.8 123.31 180 bottom
PC6381  4.7U_0603_6.3V6K  [C_0603]  237.82 130.29 180 bottom
PC6382  4.7U_0603_6.3V6K  [C_0603]  262.25 128.01 0 bottom
PC6383  4.7U_0603_6.3V6K  [C_0603]  257.88 122.04 0 bottom
PC6384  4.7U_0603_6.3V6K  [C_0603]  262.25 126.8 0 bottom
PC6385  4.7U_0603_6.3V6K  [C_0603]  232.86 130.36 180 bottom
PC6386  4.7U_0603_6.3V6K  [C_0603]  228.85 130.36 0 bottom
PC6387  4.7U_0603_6.3V6K  [C_0603]  257.88 123.24 0 bottom
PC6388  470U_D2_2VM_R4.5M~D  [C_D1]  257.77 128.77 180 bottom
PC6389  470U_D2_2VM_R4.5M~D  [C_D1]  242.12 128.77 0 bottom
PC6390  470U_D2_2VM_R4.5M~D  [C_D1]  240.82 107.61 270 top
PC6391  470U_D2_2VM_R4.5M~D  [C_D1]  232.75 100.33 270 top
PC6392  10U_0603_6.3V6M  [C_0603]  262.2 122.86 180 bottom
PC6393  10U_0603_6.3V6M  [C_0603]  262.2 124.13 180 bottom
PC6394  10U_0603_6.3V6M  [C_0603]  262.26 130.48 0 bottom
PC6395  10U_0603_6.3V6M  [C_0603]  239.02 130.29 0 bottom
PC6396  10U_0603_6.3V6M  [C_0603]  262.2 121.66 180 bottom
PC6397  10U_0603_6.3V6M  [C_0603]  262.2 125.4 180 bottom
PC6398  10U_0603_6.3V6M  [C_0603]  262.26 129.28 0 bottom
PC6399  10U_0603_6.3V6M  [C_0603]  222.64 130.36 180 bottom
PC6400  10U_0603_6.3V6M  [C_0603]  256.85 124.58 180 bottom
PC6401  10U_0603_6.3V6M  [C_0603]  257.88 125.72 0 bottom
PC6402  10U_0603_6.3V6M  [C_0603]  257.88 124.51 0 bottom
PC6403  10U_0603_6.3V6M  [C_0603]  256.8 122.04 180 bottom
PC6404  10U_0603_6.3V6M  [C_0603]  256.85 125.78 180 bottom
PC6405  10U_0603_6.3V6M  [C_0603]  262.2 120.45 180 bottom
PC6406  10U_0603_6.3V6M  [C_0603]  223.78 130.36 0 bottom
PC6407  10U_0603_6.3V6M  [C_0603]  227.78 130.36 180 bottom
PC6408  10U_0603_6.3V6M  [C_0603]  237.52 108.07 180 top
PC6409  10U_0603_6.3V6M  [C_0603]  237.52 100.26 180 top
PC6410  10U_0603_6.3V6M  [C_0603]  237.52 95.94 180 top
PC6411  10U_0603_6.3V6M  [C_0603]  237.52 94.42 180 top
PC6412  10U_0603_6.3V6M  [C_0603]  237.52 98.86 180 top
PC6413  10U_0603_6.3V6M  [C_0603]  237.52 103.56 180 top
PC6414  10U_0603_6.3V6M  [C_0603]  237.52 106.48 180 top
PC6415  0.22U_0603_25V7K  [C_0603]  300.03 52.15 180 top
PC6416  4.7U_0603_6.3V  [C_0603]  303.4 50.26 270 top
PC6417  1U_0402_25V6K  [C_0402]  289.76 43.74 0 top
PC6418  1000P_0402_50V7K  [C_0402]  289.76 41.9 0 top
PC6419  0.1U_0402_25V6  [C_0402]  288.91 39.68 0 bottom
PC6420  2200P_0402_50V7K  [C_0402]  289.77 42.83 0 top
PC6421  10U_0805_25V6K~D  [C_0805]  289.7 45.06 0 top
PC6422  10U_0805_25V6K~D  [C_0805]  289.74 46.84 0 top
PC6423  0.22U_0603_25V7K  [C_0603]  306.02 51.55 0 top
PC6425  470U_D2_2VM_R4.5M~D  [C_D1]  287.82 68.65 0 bottom
PC6426  1000P_0402_25V8J  [C_0402]  297.88 57.72 0 top
PC6427  0.1U_0603_25V7K  [C_0603]  297.33 56.65 0 top
PC6428  3300P_0805_50V7K  [C_0805]  286.53 52.61 180 top
PC6429  1U_0402_25V6K  [C_0402]  285.95 43.3 180 top
PC6430  0.1U_0402_25V6  [C_0402]  287.49 39.78 180 bottom
PC6431  2200P_0402_50V7K  [C_0402]  285.96 44.24 180 top
PC6432  10U_0805_25V6K~D  [C_0805]  286.44 45.6 180 top
PC6433  33U_D2_25VM_R40M  [C_EEFCX1E330R]  277.03 37.88 180 bottom
PC6434  47P_0402_50V8J  [C_0402]  297.79 60.07 0 top
PC6435  1000P_0402_50V7K  [C_0402]  285.97 41.51 180 top
PC6436  10U_0805_25V6K~D  [C_0805]  286.47 47.38 180 top
PC6437  1500P_0402_50V7K  [C_0402]  304.1 59.16 90 top
PC6438  470U_D2_2VM_R4.5M~D  [C_D1]  286.5 64.55 0 top
PC6439  4700P_0402_50V7K  [C_0402]  305.9 60.93 180 top
PC6440  3300P_0805_50V7K  [C_0805]  277.9 52.84 270 top
PC6441  0.01U_0402_16V  [C_0402]  301.42 60.96 0 top
PC6442  22U_0603_6.3VAM  [C_0603]  276.68 68.57 0 bottom
PC6443  22U_0603_6.3VAM  [C_0603]  276.68 67.36 0 bottom
PC6444  22U_0603_6.3VAM  [C_0603]  279.22 67.62 0 top
PC6445  22U_0603_6.3VAM  [C_0603]  279.22 68.89 0 top
PC8200  2.2U_0603_10V7K  [C_0603]  247.97 36.25 0 bottom
PC8201  2200P_0402_50V7K  [C_0402]  260.35 25.14 0 bottom
PC8202  0.1U_0402_25V6  [C_0402]  257.2 25.01 180 bottom
PC8203  10U_0805_25V6K~D  [C_0805]  260.4 26.47 0 top
PC8204  10U_0805_25V6K~D  [C_0805]  257.02 26.34 180 top
PC8205  0.1U_0402_25V6  [C_0402]  240.53 36.31 0 bottom
PC8206  0.22U_0603_25V7K  [C_0603]  247.72 32.89 0 bottom
PC8207  220U 2.5V Y D2 ESR9M H1.9 SX  [C_D2]  268.61 42.12 270 bottom
PC8208  220U 2.5V Y D2 ESR9M H1.9 SX  [C_D2]  258.22 45.52 180 bottom
PC8210  680P_0402_50V7K  [C_0402]  265.69 31.63 270 top
PC8211  0.1U_0402_25V6  [C_0402]  244.12 31.68 180 bottom
PC8212  10U_0805_25V6K~D  [C_0805]  257.02 26.34 180 bottom
PC8213  0.22U_0603_25V7K  [C_0603]  247.65 37.71 90 bottom
PC8214  10U_0805_25V6K~D  [C_0805]  260.4 26.47 0 bottom
PC8215  0.1U_0402_25V6  [C_0402]  241.58 36.24 180 top
PC8216  47P_0402_50V8J  [C_0402]  243.21 38.2 90 bottom
PC8217  2200P_0402_50V7K  [C_0402]  241.58 33.57 180 top
PC8218  0.1U_0402_25V6  [C_0402]  244.24 38.76 180 top
PC8219  680P_0402_50V7K  [C_0402]  251.91 31.63 270 top
PC8220  1000P_0402_50V7K  [C_0402]  257.2 25.01 180 top
PC8221  1U_0402_25V6K  [C_0402]  260.35 25.14 0 top
PC8222  0.1U_0402_25V6  [C_0402]  238.25 31.55 0 bottom
PC9000  1U_0603_10V7K  [C_0603]  29.54 16.08 270 bottom
PC9001  0.1U_0402_16V7K  [C_0402]  28.33 14.65 90 bottom
PC9002  2200P_0402_25V7K  [C_0402]  28.33 17.4 270 bottom
PC9003  1U_0603_10V7K  [C_0603]  33.66 21.01 270 bottom
PD1  SM24_SOT23  [TP0610K-T1-E3_SOT23-3]  321 51.03 180 top
PD2  -  [TVNST52302AB0_SOT523-3]  83.4 14.88 180 top
PD3  -  [TVNST52302AB0_SOT523-3]  79.22 9.39 180 top
PD5  -  [BAS40CW_SOT323-3]  294.18 44.19 180 top
PD100  -  [BAS40CW_SOT323-3]  60.51 47.04 90 top
PD101  -  [LL4148_LL34-2]  53.5 19.18 0 bottom
PD700  -  [BAT54CW_SOT323-3]  60.27 20.82 90 bottom
PH1  100K_0402_1%_B25/50 4250K  [R_0402]  153.24 112.22 270 top
PH500  100K_0402_1%_TSM0B104F4251RZ  [R_0402]  186.55 134.27 270 bottom
PH501  220K_0402_5%_ERTJ0EV224J  [R_0402]  149.42 134.12 270 bottom
PH502  220K_0402_5%_ERTJ0EV224J  [R_0402]  140.12 135.03 0 bottom
PH503  220K_0402_5%_ERTJ0EV224J  [R_0402]  154.46 150.95 0 bottom
PH504  220K_0402_5%_ERTJ0EV224J  [R_0402]  146.84 152.09 270 bottom
PH6000  470K_0402_5%_B25/50 4700K  [R_0402]  251.23 146.8 180 bottom
PJ800  -  [JUMP_43X39]  247.61 41.77 180 bottom
PJP100  -  [JUMP_43X118]  40.36 47.4 180 top
PJP101  -  [JUMP_43X118]  40.36 42.18 180 top
PJP102  -  [JUMP_43X118]  45.6 21.98 90 top
PJP104  -  [JUMP_43X118]  40.33 21.98 90 top
PJP200  -  [JUMP_43X118]  97.23 32.06 0 top
PJP201  -  [JUMP_43X118]  97.23 26.72 0 top
PJP202  -  [JUMP_43X39]  93.1 51.87 90 bottom
PJP203  -  [JUMP_43X39]  89.06 33.33 90 top
PJP300  -  [JUMP_43X118]  247.4 27.95 90 bottom
PJP301  -  [JUMP_43X39]  259.28 16.58 270 top
PJP302  -  [JUMP_43X118]  242.2 27.95 90 bottom
PJP504  -  [JUMP_43X39]  118.31 123.13 270 bottom
PJP505  -  [JUMP_43X118]  123.7 103.6 270 bottom
PJP801  -  [JUMP_43X79]  234.13 47.76 90 bottom
PJP802  -  [JUMP_43X39]  233.83 37.65 180 bottom
PJP803  -  [JUMP_43X79]  220.99 46.88 90 bottom
PJP1300  -  [JUMP_43X79]  102.78 42.41 0 bottom
PJP1301  -  [JUMP_43X79]  101.62 56.76 270 bottom
PJP8200  -  [JUMP_43X39]  260.66 23.55 0 bottom
PJP8201  -  [JUMP_43X118]  263.33 46.6 90 bottom
PJP8202  -  [JUMP_43X118]  268.61 46.62 90 bottom
PJP9000  -  [JUMP_43X39]  31.25 14.9 90 bottom
PJP9001  -  [JUMP_43X39]  31.89 21.38 90 bottom
PJPDC1  ACES_50290-01301-P01  [ACES_50290-01301-P01_13P-T]  66.32 45.9 0 bottom
PL1  FBMA-L11-453215-121LMA90T_2  [9A_Z80_1812_2P]  81.35 35.53 180 bottom
PL2  BLM15HG601SN1D_2P  [MURAT_BLM15HG601SN1D_2P]  63.32 48.32 90 bottom
PL3  FBMA-L11-453215-121LMA90T_2  [9A_Z80_1812_2P]  81.36 39.37 180 bottom
PL4  9A Z80 10M 1812_2P  [9A_Z80_1812_2P]  83.33 26.22 270 bottom
PL5  9A Z80 10M 1812_2P  [9A_Z80_1812_2P]  87.13 26.22 270 bottom
PL100  1UH_6.6A_20%_5X5X3_M  [L_5X5X3_M_2P]  53.41 34.85 90 bottom
PL101  2.2UH_PCMB104T-2R2MS_12A_20%  [CYNTE_PCMB104T-2R2MS_2P]  49.54 20.92 90 bottom
PL102  2.2UH_PCMB104T-2R2MS_12A_20%  [CYNTE_PCMB104T-2R2MS_2P]  45.22 35.71 90 bottom
PL201  1UH_11A_20%_7X7X3_M  [L_7X7X3_M_2P]  97.15 36.8 180 bottom
PL300  1UH_11A_20%_7X7X3_M  [L_7X7X3_M_2P]  255 21.26 180 bottom
PL500  FBMA-L11-453215800LMA90T_2P  [KC_FBMA-L11-453215800LMA90T_2P]  137.17 143.9 90 bottom
PL501  0.15UH_MMD-06DZER15MEM1L__36A_20%  [CYNTE_PCME064T-R15MS0R667_2P]  151.02 142.42 270 bottom
PL502  0.15UH_MMD-06DZER15MEM1L__36A_20%  [CYNTE_PCME064T-R15MS0R667_2P]  156.32 137.34 0 bottom
PL503  0.15UH_MMD-06DZER15MEM1L__36A_20%  [CYNTE_PCME064T-R15MS0R667_2P]  171.62 137.34 180 bottom
PL505  0.15UH_MMD-06DZER15MEM1L__36A_20%  [CYNTE_PCME064T-R15MS0R667_2P]  143.95 142.42 270 bottom
PL506  0.15UH_MMD-06DZER15MEM1L__36A_20%  [CYNTE_PCME064T-R15MS0R667_2P]  176.93 138.96 270 bottom
PL508  0.47UH_NA__12.2A_20%  [MAG_MMD05CZR47M_4P]  183.21 137.8 270 bottom
PL509  1UH_PCMB042T-1R0MS_4.5A_20%  [CYNTE_PCMB042T-1R0MS_2P]  126.18 113.22 270 bottom
PL700  2.2UH_PCMB104T-2R2MS_12A_20%  [CYNTE_PCMB104T-2R2MS_2P]  65.72 25.71 0 bottom
PL701  1UH_6.6A_20%_5X5X3_M  [L_5X5X3_M_2P]  56.57 30.92 0 bottom
PL800  1UH_PCMB042T-1R0MS_4.5A_20%  [CYNTE_PCMB042T-1R0MS_2P]  245.79 47.5 180 bottom
PL801  1UH_PCMB042T-1R0MS_4.5A_20%  [CYNTE_PCMB042T-1R0MS_2P]  230.38 48.77 180 bottom
PL6100  0.22UH_MMD12DZNR22MEX_40A_20%  [MAG_MMD12DZNR22MEX_4P]  257.25 144.9 270 bottom
PL6101  0.22UH_MMD12DZNR22MEX_40A_20%  [MAG_MMD12DZNR22MEX_4P]  243.47 144.84 270 bottom
PL6200  0.22UH_MMD12DZNR22MEX_40A_20%  [MAG_MMD12DZNR22MEX_4P]  229.75 144.78 270 bottom
PL6201  0.22UH_MMD12DZNR22MEX_40A_20%  [MAG_MMD12DZNR22MEX_4P]  216.1 144.78 270 bottom
PL6400  0.22UH_MMD-10DZ-R22MES1L_35A_20%  [MAG_MMD-10DZ-R22MES1L_2P]  290.24 54.47 90 bottom
PL6401  0.22UH_MMD-10DZ-R22MES1L_35A_20%  [MAG_MMD-10DZ-R22MES1L_2P]  279.64 54.23 90 bottom
PL8200  S COIL 0.47UH +-20% PCMB063T-R47MS 18A  [L_7X7X3_M_2P]  262.14 35 90 bottom
PL8201  S COIL 0.47UH +-20% PCMB063T-R47MS 18A  [L_7X7X3_M_2P]  254.39 35.06 90 bottom
PQ2  MMST3904-7-F_SOT323-3  [RHU002N06_SOT323-3]  316.09 53.04 270 top
PQ3  -  [SI3457CDV-T1-GE3_TSOP6]  68.54 12.69 0 top
PQ4  L2N7002WT1G 1N SC-70-3  [SSM3K7002FU_SC70-3]  70.56 11.1 180 top
PQ7  FDV301N_G 1N SOT23-3  [FDV301N_NL_SOT23-3]  316.44 49.66 90 top
PQ8  L2N7002WT1G 1N SC-70-3  [SSM3K7002FU_SC70-3]  74.24 9.96 270 top
PQ9  L2N7002DW1T1G_SC88-6  [DMN65D8LDW-7_SOT363-6]  120.12 79.62 90 top
PQ100  -  [AON7380_DFN3X3-8-5]  50.68 30.85 0 top
PQ101  -  [AON7508_DFN8-5]  48.78 33.39 180 top
PQ102  -  [AON7380_DFN3X3-8-5]  44.48 38.93 0 top
PQ103  -  [AON7508_DFN8-5]  47.21 35.21 90 top
PQ200  -  [AON7408L_DFN8-5]  91.91 40.25 180 top
PQ201  -  [AON7752_DFN3X3EP8-5]  93.74 37.43 0 top
PQ202  L2N7002DW1T1G_SC88-6  [2N7002DW-7-F_SOT363-6]  104.99 56.48 270 top
PQ300  -  [AON7408L_DFN8-5]  254.1 23.52 270 top
PQ301  -  [AON7752_DFN3X3EP8-5]  256.89 17.86 90 top
PQ700  L2N7002WT1G 1N SC-70-3  [SSM3K7002FU_SC70-3]  66.3 33.33 270 bottom
PQ701  -  [EMB04N03H_EDFN5X6-8-5]  69.76 40.63 270 top
PQ702  -  [EMB04N03H_EDFN5X6-8-5]  67.49 39.78 270 bottom
PQ703  -  [EMB04N03H_EDFN5X6-8-5]  81.57 33.65 270 top
PQ704  AON6354_N_DFN56-8-5  [AON6414AL_DFN8-5]  69.67 21.39 0 top
PQ705  L2N7002WT1G 1N SC-70-3  [SSM3K7002FU_SC70-3]  63.21 20.56 90 top
PQ706  -  [AON7426_DFN3X3EP8-5]  65.16 25.39 270 top
PQ707  -  [EMB04N03H_EDFN5X6-8-5]  69.73 36 90 bottom
PQ708  -  [EMB04N03H_EDFN5X6-8-5]  67.08 36.9 90 top
PQ6400  -  [AON6962_DFN5X6D-8-7]  289.08 46.8 90 bottom
PQ6401  -  [AON6962_DFN5X6D-8-7]  289.01 41.04 90 bottom
PQ6402  -  [AON6962_DFN5X6D-8-7]  287.14 44.82 270 bottom
PQ6403  -  [AON6962_DFN5X6D-8-7]  287.08 50.56 270 bottom
PQ8200  -  [AON6962_DFN5X6D-8-7]  259.87 28.25 90 bottom
PQ8201  -  [AON6962_DFN5X6D-8-7]  257.54 31.93 270 bottom
PQ8202  DMN53D0LDW-7 2N SOT363-6  [2N7002DW-7-F_SOT363-6]  239.1 32.53 180 bottom
PQ8203  DMN53D0LDW-7 2N SOT363-6  [2N7002DW-7-F_SOT363-6]  276.99 152.33 270 top
PR2  1K_0402_1%  [R_0402]  293.95 41.46 0 top
PR3  2.2K_0402_1%  [R_0402]  312.56 50.33 90 top
PR4  33_0402_5%  [R_0402]  312.56 48.56 90 top
PR6  100K_0402_1%  [R_0402]  318.3 49.46 270 top
PR8  10K_0402_1%  [R_0402]  314.78 53.28 270 top
PR9  15K_0402_1%  [R_0402]  318.3 51.24 270 top
PR11  1K_0402_1%  [R_0402]  296.03 43.3 0 top
PR12  100K_0402_1%  [R_0402]  73.81 12.25 180 top
PR13  100K_0402_1%  [R_0402]  71.7 12.23 90 top
PR14  100K_0402_1%  [R_0402]  67.95 9.97 270 top
PR16  10K_0402_1%  [R_0402]  81.87 10.71 180 top
PR17  0_0402_5%  [R0402_0OHM]  68.86 10.85 180 top
PR19  100_0402_1%  [R_0402]  82.48 13.62 90 top
PR21  100_0402_1%  [R_0402]  81.59 13.62 90 top
PR22  100_0402_1%  [R_0402]  79.79 12.63 270 top
PR23  110K_0402_1%  [R_0402]  292.26 7.2 90 top
PR24  14.7K_0402_1%  [R_0402]  312.71 53.28 270 top
PR25  12.1K_0402_1%  [R_0402]  313.64 53.28 270 top
PR26  100K_0402_1%  [R_0402]  294.14 8.12 270 top
PR27  0_0402_5%  [R0402_0OHM]  116.33 83.18 0 top
PR28  100K_0402_1%  [R_0402]  77.37 10.53 270 top
PR29  1M_0402_1%  [R_0402]  117.23 80.29 90 top
PR31  1M_0402_1%  [R_0402]  116.34 81.21 270 top
PR32  10K_0402_1%  [R_0402]  121.14 82.88 270 top
PR33  100K_0402_1%  [R_0402]  121.07 78.46 90 top
PR100  0_0402_5%  [R0402_0OHM]  59.65 49.68 270 top
PR101  10K_0402_1%  [R_0402]  57.12 51.27 180 bottom
PR102  15.8K_0402_1%  [R_0402]  50.88 51.22 180 bottom
PR103  14.3K_0402_1%  [R_0402]  55.19 51.25 270 bottom
PR104  10K_0402_1%  [R_0402]  52.02 50.33 90 bottom
PR105  78.7K_0402_1%  [R_0402]  57.11 50.4 180 bottom
PR106  57.6K_0402_1%  [R_0402]  49.97 50.33 0 bottom
PR107  200_0402_1%  [R_0402]  50.12 48.3 180 bottom
PR108  0_0603_5%  [R_0603]  58.62 46.41 180 bottom
PR109  0_0603_5%  [R_0603]  50.74 46.33 180 bottom
PR110  4.7_1206_5%  [R_1206]  44.49 28.66 90 top
PR111  4.7_1206_5%  [R_1206]  42.62 36.84 270 top
PR112  0_0402_5%  [R0402_0OHM]  60.57 49.68 270 top
PR113  2.2K_0402_1%  [R_0402]  61.91 46.15 90 top
PR114  0_0402_5%  [R0402_0OHM]  58.77 49.68 270 top
PR115  1M_0402_1%  [R_0402]  62.79 46.15 90 top
PR116  200K_0402_1%  [R_0402]  62.15 47.94 0 top
PR200  2.2_0603_5%  [R_0603]  88.21 45.58 0 bottom
PR201  22.6K_0402_1%  [R_0402]  97.35 42.6 270 bottom
PR202  4.7_1206_5%  [R_1206]  97.61 40.06 270 top
PR203  5.1_0603_5%  [R_0603]  96.21 41.2 90 bottom
PR204  2.2_0603_5%  [R_0603]  92.27 41.2 90 bottom
PR205  12K_0402_1%  [R_0402]  95.02 49.84 180 bottom
PR206  887K_0402_1%  [R_0402]  96.71 44.49 180 bottom
PR207  20K_0402_1%  [R_0402]  95.02 48.95 180 bottom
PR208  0_0402_5%  [R0402_0OHM]  96.8 45.39 180 bottom
PR209  0_0402_5%  [R_0402]  95.88 48.19 0 bottom
PR210  100K_0402_1%  [R_0402]  96.71 43.59 180 bottom
PR211  0_0402_5%  [R0402_0OHM]  95.88 49.14 0 bottom
PR212  1K_0402_1%  [R_0402]  102.28 52.78 90 top
PR213  60.4K_0402_1%  [R_0402]  104.83 51.87 0 top
PR214  1K_0402_1%  [R_0402]  106.17 53.18 90 top
PR215  60.4K_0402_1%  [R_0402]  104.99 53.18 90 top
PR216  100K_0402_1%  [R_0402]  103.11 54.59 0 top
PR217  100K_0402_1%  [R_0402]  107.91 53.8 90 top
PR300  100K_0402_1%  [R_0402]  240.92 18.72 0 top
PR301  100K_0402_1%  [R_0402]  244.56 23.88 180 top
PR302  2.2_0603_5%  [R_0603]  246.52 23.74 0 top
PR303  97.6K_0402_1%  [R_0402]  241.82 22.23 270 top
PR305  4.7_1206_5%  [R_1206]  257.95 22.98 270 bottom
PR306  470K_0402_1%  [R_0402]  243.2 16.69 0 top
PR307  4.99K_0402_1%  [R_0402]  241.83 16.06 180 top
PR308  10K_0402_1%  [R_0402]  241.83 16.95 180 top
PR500  100_0402_1%  [R_0402]  126.81 133.96 0 top
PR501  12K_0402_1%  [R_0402]  125.03 133.43 90 top
PR502  7.5K_0603_1%  [R_0603]  180.91 134.1 90 top
PR503  10_0402_1%  [R_0402]  125.92 133.43 90 top
PR504  499_0402_1%  [R_0402]  121.45 136.52 270 bottom
PR505  100_0402_1%  [R_0402]  122.31 135.6 90 bottom
PR506  45.3_0402_1%  [R_0402]  123.18 136.52 270 bottom
PR507  45.3_0402_1%  [R_0402]  124.05 136.52 270 bottom
PR508  0_0402_5%  [R0402_0OHM]  127.75 135.28 180 bottom
PR509  1K_0402_5%  [R_0402]  126.88 136.6 90 bottom
PR510  0_0402_5%  [R0402_0OHM]  129.02 133.45 90 top
PR511  1.58K_0402_1%  [R_0402]  127.75 136.6 90 bottom
PR512  28.7K_0402_1%  [R_0402]  125.99 136.27 90 top
PR513  100_0402_1%  [R_0402]  121.45 136.52 270 top
PR514  100_0402_1%  [R_0402]  126.81 133.07 0 top
PR515  49.9_0402_1%  [R_0402]  124.18 136.52 270 top
PR516  10K_0402_1%  [R_0402]  125.1 136.27 90 top
PR517  0_0402_5%  [R0402_0OHM]  123.31 135.6 90 top
PR518  12.4K_0402_1%  [R_0402]  125.99 137.19 270 bottom
PR519  10_0402_1%  [R_0402]  122.44 136.52 270 top
PR520  1.5K_0402_1%  [R_0402]  129.73 135.72 180 top
PR521  100_0402_1%  [R_0402]  128.81 137.47 0 bottom
PR522  34.8K_0402_1%  [R_0402]  123.05 139.04 90 bottom
PR523  0_0402_5%  [R0402_0OHM]  129.73 137.47 180 top
PR524  0_0402_5%  [R0402_0OHM]  125.1 137.19 270 bottom
PR525  0_0402_5%  [R0402_0OHM]  128.81 138.76 0 top
PR526  100_0402_1%  [R_0402]  120.58 135.97 270 top
PR527  1.37K_0402_1%  [R_0402]  129.73 139.63 180 bottom
PR528  100_0402_1%  [R_0402]  129.73 138.76 180 bottom
PR529  0_0402_5%  [R0402_0OHM]  120.55 138.29 270 top
PR530  1.37K_0402_1%  [R_0402]  120.53 138.26 180 bottom
PR531  0_0402_5%  [R0402_0OHM]  119.72 133.71 180 top
PR532  100_0402_1%  [R_0402]  118.83 134.57 90 top
PR533  49.9_0402_1%  [R_0402]  128.84 142.24 0 top
PR534  26.7K_0402_1%  [R_0402]  127.29 142.14 90 bottom
PR535  3.65K_0402_1%  [R_0402]  128.8 142.23 0 bottom
PR536  1K_0402_1%  [R_0402]  129.75 141.38 180 top
PR537  49.9_0402_1%  [R_0402]  117.94 134.6 270 top
PR538  30.9K_0402_1%  [R_0402]  120.38 140.52 0 bottom
PR539  1K_0402_1%  [R_0402]  117.05 135.46 0 top
PR540  3.65K_0402_1%  [R_0402]  118.55 141.91 90 bottom
PR541  32.4K_0402_1%  [R_0402]  129.73 144.2 270 top
PR542  12.1K_0402_1%  [R_0402]  118.55 144.55 0 bottom
PR543  75K_0402_1%  [R_0402]  129.73 143.28 0 bottom
PR544  100K_0402_1%  [R_0402]  119.47 145.44 180 bottom
PR545  1K_0402_1%  [R_0402]  120.73 148.78 270 top
PR546  90.9K_0603_1%  [R_0603]  131.72 145.22 180 bottom
PR547  165K_0402_1%  [R_0402]  130.64 144.17 180 bottom
PR548  249K_0402_1%  [R_0402]  118.55 146.31 0 bottom
PR549  90.9K_0603_1%  [R_0603]  121.62 150.18 0 bottom
PR550  90.9K_0603_1%  [R_0603]  131.72 146.42 180 bottom
PR551  90.9K_0603_1%  [R_0603]  131.71 147.63 180 bottom
PR552  0_0402_5%  [R0402_0OHM]  149.97 152.05 270 bottom
PR553  2_0603_5%  [R_0603]  151.01 152.75 270 bottom
PR554  3.9_0603_1%  [R_0603]  153.45 152.37 270 bottom
PR555  10_1206_5%  [R_1206]  150.18 143.33 0 top
PR556  0_0402_5%  [R0402_0OHM]  149.11 152.05 270 bottom
PR557  2.21K_0402_1%  [R_0402]  129.42 145.49 180 top
PR558  118K_0402_1%  [R_0402]  124.82 146.13 270 bottom
PR559  10_0402_1%  [R_0402]  150.67 138.55 180 top
PR560  24.9K_0402_1%  [R_0402]  123.48 147.91 90 top
PR561  97.6K_0402_1%  [R_0402]  123.5 144.88 270 bottom
PR562  97.6K_0402_1%  [R_0402]  122.61 147.91 90 top
PR563  0_0402_5%  [R0402_0OHM]  157.34 148.72 270 bottom
PR564  3.9_0603_1%  [R_0603]  161.22 149.37 270 bottom
PR565  10_1206_5%  [R_1206]  158.01 139.52 0 top
PR566  0_0402_5%  [R0402_0OHM]  156.47 148.72 270 bottom
PR567  0_0402_5%  [R0402_0OHM]  155.38 152.73 180 bottom
PR568  0_0402_5%  [R0402_0OHM]  145.85 152.12 270 bottom
PR569  10_0402_1%  [R_0402]  159.24 135.21 0 top
PR570  61.9K_0402_1%  [R_0402]  148.85 150.55 270 top
PR571  1K_0402_1%  [R_0402]  126.97 148.78 270 bottom
PR572  90.9K_0603_1%  [R_0603]  131.71 148.83 180 bottom
PR573  0_0402_5%  [R0402_0OHM]  164.94 148.68 270 bottom
PR574  3.9_0603_1%  [R_0603]  168.86 149.37 270 bottom
PR575  10_1206_5%  [R_1206]  165.6 139.52 0 top
PR576  0_0402_5%  [R0402_0OHM]  164.08 148.68 270 bottom
PR577  2.2_0603_5%  [R_0603]  125.91 149.33 270 bottom
PR578  24.9K_0402_1%  [R_0402]  121.75 147.91 90 top
PR579  10_0402_1%  [R_0402]  166.09 135.12 180 top
PR580  4.32K_0402_1%  [R_0402]  124.34 147.91 90 top
PR581  2.21K_0402_1%  [R_0402]  129.42 147.6 180 top
PR582  2.21K_0402_1%  [R_0402]  129.42 148.87 180 top
PR583  3.9_0603_1%  [R_0603]  144.82 152.62 270 bottom
PR584  4.7_1206_5%  [R_1206]  142.66 143.28 0 top
PR585  0_0402_5%  [R0402_0OHM]  140.52 152.33 270 bottom
PR586  61.9K_0402_1%  [R_0402]  154.47 151.84 0 bottom
PR587  2.21K_0402_1%  [R_0402]  129.42 146.38 180 top
PR588  10_0402_1%  [R_0402]  143.14 138.59 180 top
PR589  25.5K_0402_1%  [R_0402]  123.07 145.75 180 bottom
PR590  0_0402_5%  [R0402_0OHM]  141.39 152.33 270 bottom
PR591  0_0402_5%  [R0402_0OHM]  173.68 148.57 270 bottom
PR592  3.9_0603_1%  [R_0603]  177.36 149.43 270 bottom
PR593  10_1206_5%  [R_1206]  174.52 139.52 0 top
PR594  0_0402_5%  [R0402_0OHM]  172.82 148.57 270 bottom
PR595  2.21K_0402_1%  [R_0402]  122.16 149.1 0 bottom
PR596  100K_0402_1%  [R_0402]  127.47 144.73 90 bottom
PR597  10_0402_1%  [R_0402]  174.98 135.12 180 top
PR598  100K_0402_1%  [R_0402]  129.42 147.25 180 bottom
PR599  100K_0402_1%  [R_0402]  129.42 149 180 bottom
PR600  100K_0402_1%  [R_0402]  129.42 150.78 180 bottom
PR601  0_0402_5%  [R0402_0OHM]  150.66 139.42 180 top
PR602  0_0402_5%  [R0402_0OHM]  157.95 136.15 180 top
PR603  0_0402_5%  [R0402_0OHM]  168.69 136.38 270 top
PR604  0_0402_5%  [R0402_0OHM]  174.99 135.99 180 top
PR605  0_0402_5%  [R0402_0OHM]  143.11 139.55 180 top
PR700  1M_0402_1%  [R_0402]  63.56 33.64 90 top
PR701  3M_0402_5%  [R_0402]  64.5 34.54 270 top
PR702  0.005_2512_1%  [R_2512_4P]  58.75 44.12 180 bottom
PR703  0_0402_5%  [R0402_0OHM]  59.63 29.03 270 top
PR704  0_0402_5%  [R0402_0OHM]  60.51 29.03 270 top
PR705  4.12K_0603_1%  [R_0603]  57.07 29.4 270 top
PR706  4.12K_0603_1%  [R_0603]  58.29 29.4 270 top
PR707  10_1206_1%  [R_1206]  62.02 20.51 90 bottom
PR708  2.2_0603_5%  [R_0603]  62.81 23.49 180 top
PR709  20K_0402_1%  [R_0402]  59.25 20.39 270 top
PR710  5.11K_0402_1%  [R_0402]  63.64 18.71 90 top
PR711  3.16K_0402_1%  [R_0402]  60.14 20.39 270 top
PR712  0.01_1206_1%  [R_1206_4P-D]  79.83 27.28 270 bottom
PR713  4.7_1206_5%  [R_1206]  67.38 21.39 180 top
